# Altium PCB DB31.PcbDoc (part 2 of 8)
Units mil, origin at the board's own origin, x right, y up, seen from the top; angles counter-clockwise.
Board outline 3236.22 x 4456.69 mil, 8 copper layers (Top Layer, MidLayer1, MidLayer2, GND-Layer5, MidLayer3, VCC, MidLayer4, Bottom Layer), stack 61.8 mil thick; 226 components, 469 nets, 1815 pads, 1562 vias.
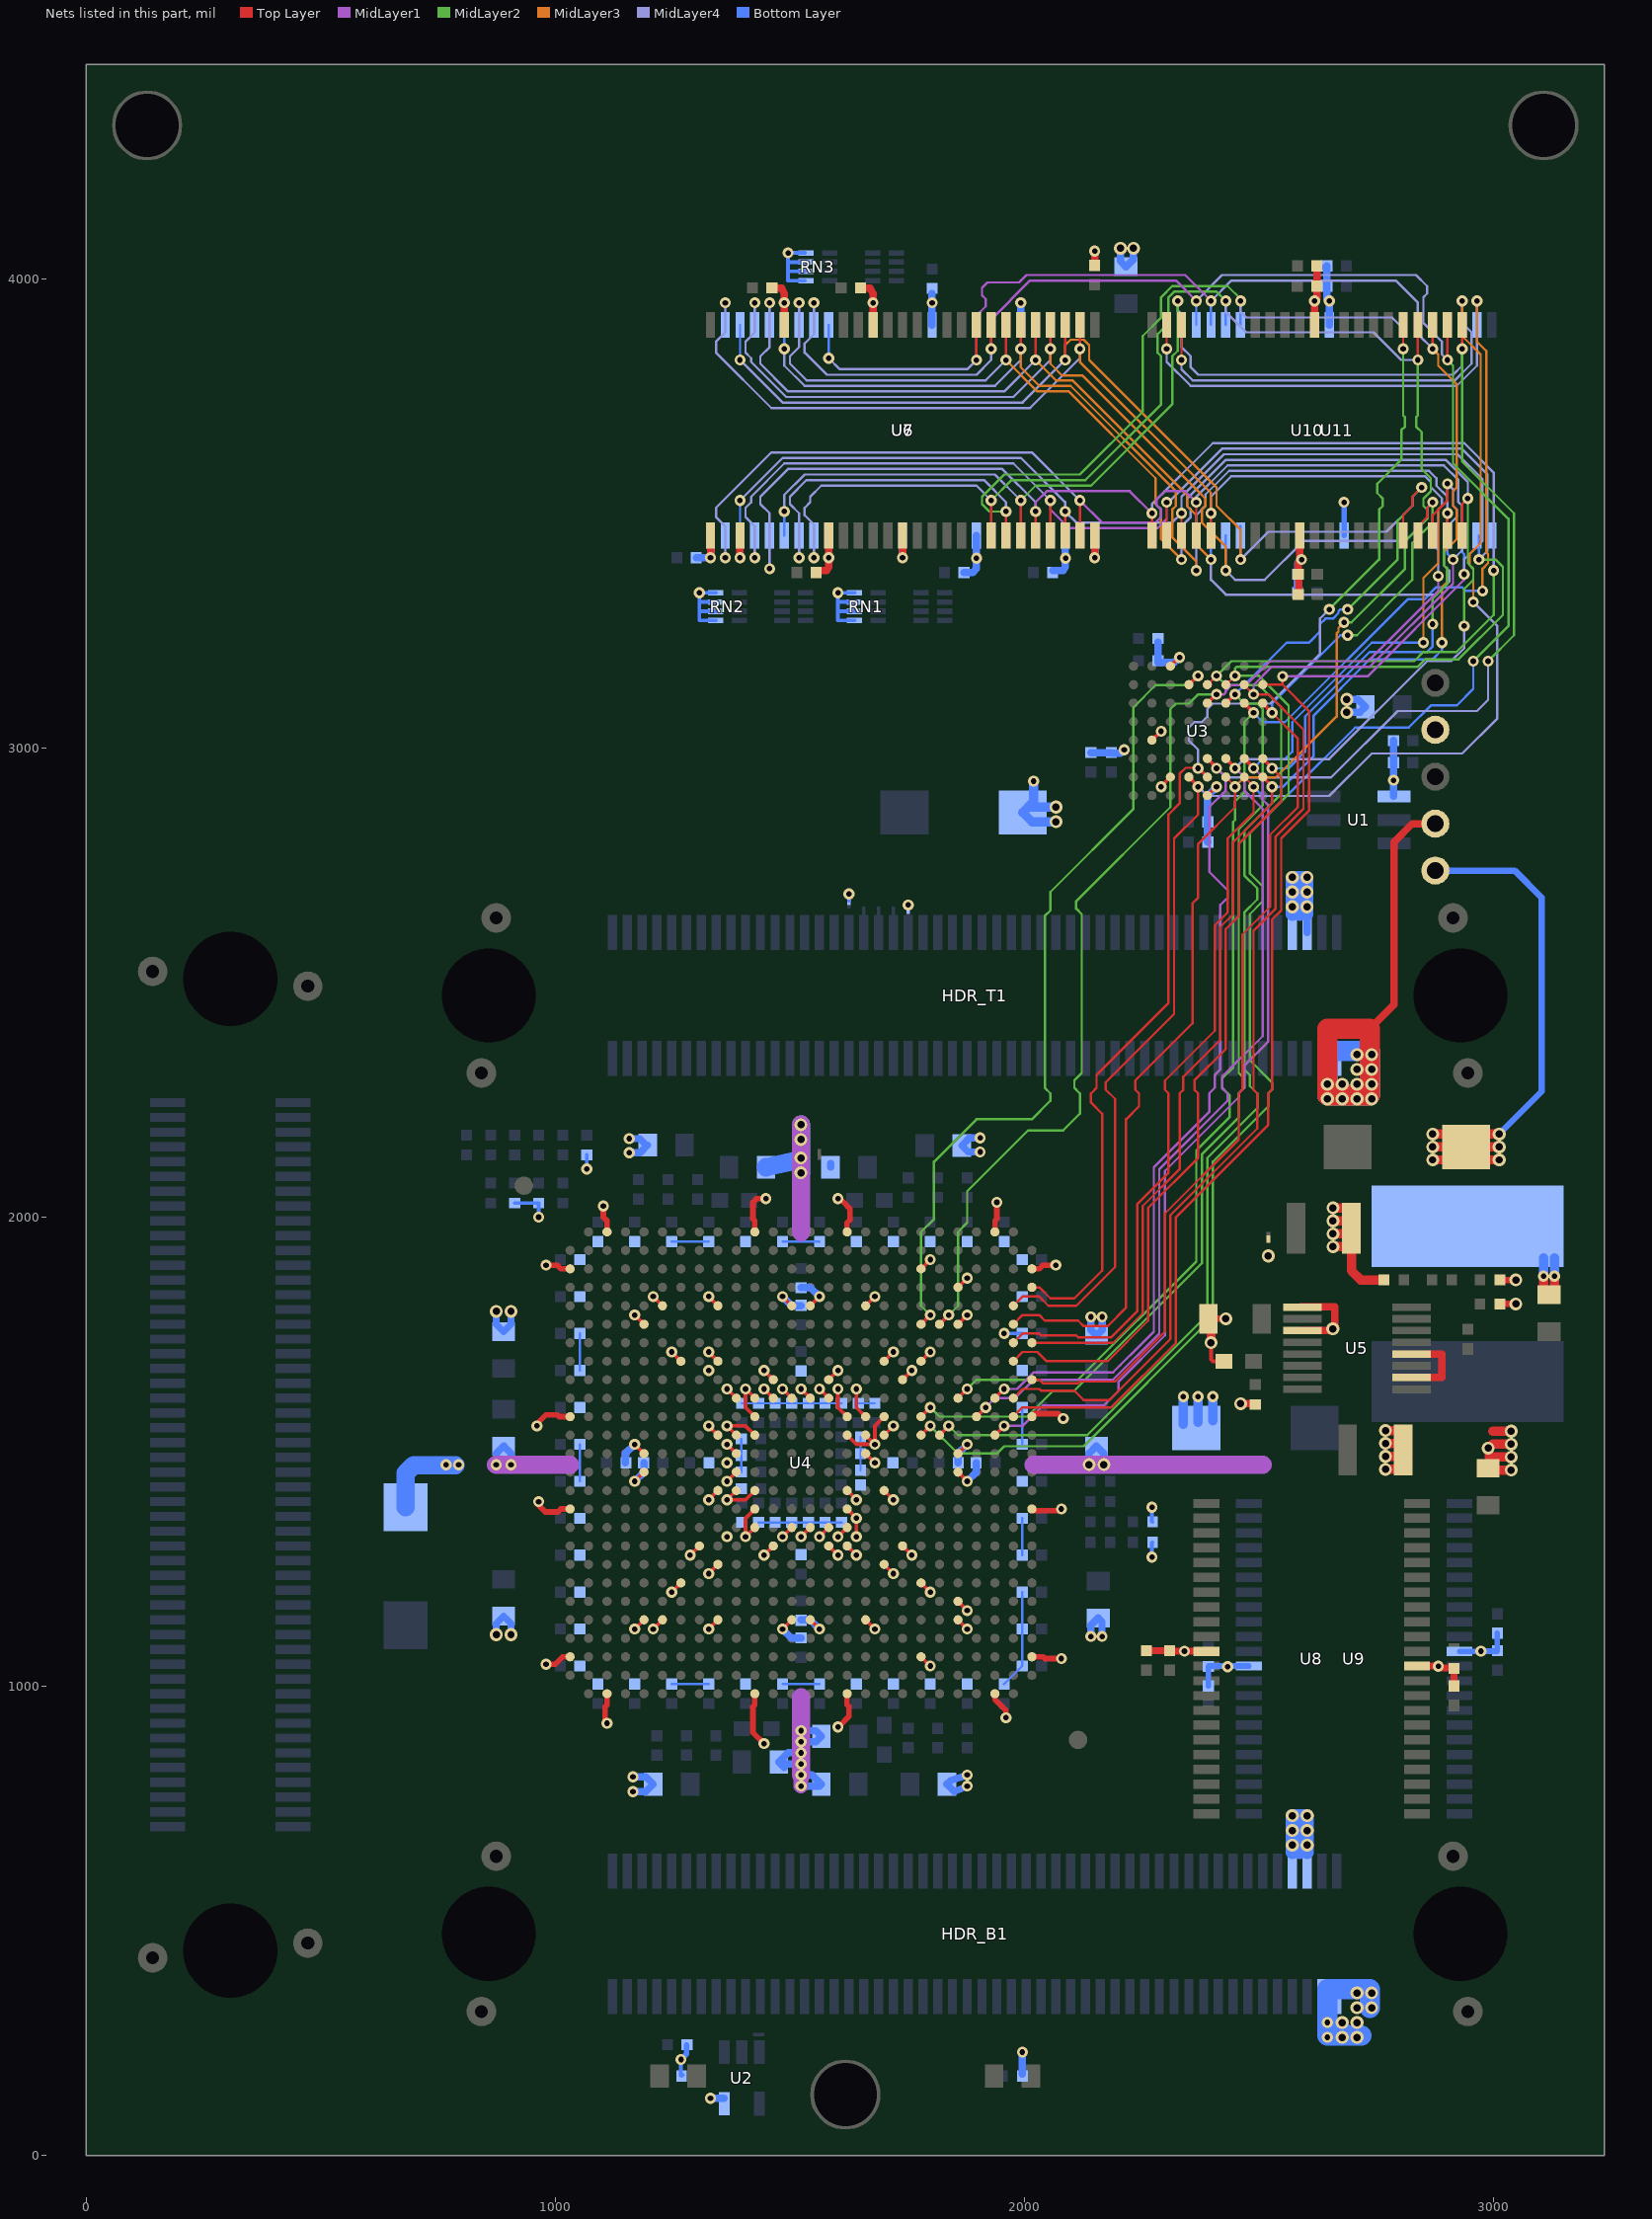
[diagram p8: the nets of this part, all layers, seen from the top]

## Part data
"Altium Logo Bot1" "Altium Logo Top1": library part D-000-0003, "Altium Logo for PCB"
C1 C7 C8 C9 C10 C11 C12 C13 C14 C15 C16 C17 C18 C19 C43 C44 C45 C46 C47 C48 C49 C50 C51 C52 C53 C54 C55 C56 C57 C58 C101 C102 C103 C107 C108 C112 C116 C120 C134 C135 C136 C137 C142 C143 C146 C147 C150 C151 C152 C153: library part D-101-0080, "Capacitor, Ceramic, 0.1uF 10% 16V 0402 (1005) X7R"
C2 C20 C21 C22 C23 C24 C25 C26 C27 C28 C29 C30 C31 C32 C33 C34 C59 C60 C61 C62 C63 C64 C65 C66 C67 C68 C69 C70 C71 C72 C73 C74 C75 C76 C77 C78 C79 C80 C81 C82 C83 C84 C85 C86 C87 C88 C89 C90 C91 C92 C93 C94 C95 C96 C97 C98 C104 C105 C106 C109 C113 C117 C121 C138 C139 C140 C141 C144 C145 C148 C149 C154 C155 C156 C157: library part D-101-0077, "Capacitor, Ceramic, 10nF 10% 16V 0402 (1005) X7R"
C3 C99 C100 C128: library part D-101-0088, "Capacitor, Tantalum, 220uF 10% 10V MCCT-D (7343-31)"
C4 C5 C6 C35 C36 C37 C38 C39 C40 C41 C42 C124 C125 C129 C131: library part D-101-0087, "Capacitor, Ceramic, 10uF 10% 10V 0805 (2012) X5R"
C110 C114 C118 C122: library part D-101-0030, "Capacitor, Ceramic, 1nF 10% 50V 0402 (1005) X7R"
C111 C115 C119 C123 C127: library part D-101-0095, "Capacitor, Ceramic, 2.2uF 10% 10V 0603 (1608) X5R"
C126: library part D-101-0069, "Capacitor, Ceramic, 470pF 5% 50V 0402 (1005) COG"
C130 C132: library part D-101-0021, "Capacitor, Ceramic, 22uF -20%/+80% 10V 1210 (3225) Y5V"
C133: library part D-101-0027, "Capacitor, Ceramic, 1uF 10% 25V 1206 (3216) X7R"
HDR_B1 HDR_L1 HDR_T1: library part D-300-0025, "Connector, Molex Docking Station 100 Pin Male 54075"
L1 L2 L3 L4: library part D-102-0002, "Inductor, Ferrite Bead 1K@100MHz 300mA 0805 (2012) BMB2A1000LN2"
L5: library part D-102-0004, "Inductor, 2.2uH, 15A, 4R2, SMD"
LED1: library part D-153-0004, "LED, Green 0805 (2012) KP-2012SGD"
LED2: library part D-153-0003, "LED, Red 0805 (2013) HSMH-C170"
MH1 MH2 MH3: library part D-001-0001, "Mounting Hole, M3 Screw, Plated, Square Pad"
NT1 NT2 NT3 NT4 NT5 NT6 NT7 NT8: library part D-002-0002, "Net-Tie, Surface Mount, 2 x 0.4mm x 0.2mm SMT Pads - For 0.2mm Track"
R1 R2: library part D-100-0111, "Resistor, 270R 1% 0402 (1005)"
R3 R4 R5 R8 R11: library part D-100-0088, "Resistor, 4K7 1% 0402 (1005)"
R6 R7 R9 R10 R12 R13 R14 R15 R16 R17 R18: library part D-100-0131, "Resistor, 100R 1% 0402 (1005)"
R19: library part D-100-0128, "Resistor, 10R 1% 0402 (1005)"
R20 R22: library part D-100-0105, "Resistor, 2K7 1% 0402 (1005)"
R21: library part D-100-0109, "Resistor, 27K 1% 0402 (1005)"
R23: library part D-100-0132, "Resistor, 100K 1% 0402 (1005)"
RN1 RN2 RN3 RN4 RN5 RN6: library part D-104-0001, "Resistor Network, Isolated, 4 x 100R, 5%, SMD 0402 x 4"
TP1 TP2 TP3 TP4 TP5: library part D-006-0000, "Test Point, PCB Mount with Silkscreen Box"
U1: library part D-263-0002, "Dual Addressable Switch Plus 1KB Memory"
U2: library part D-205-0001, "SN74LVC1G04DBV, Single Inverter Gate, 1.65-V to 5.5-V"
U3: library part D-262-0001, "S29GL256N11FFIV10, 256 Megabit (16M x 16) 3.0V Page Mode Flash Memory"
U4: library part D-241-0004, "FPGA, Altera Cyclone2-35 F672"
U5: library part D-204-0002, "MAX1831EEE, 3A, 1MHz, Low-Voltage, Step-Down Regulators with Synchronous Rectification and Internal Switches"
U6 U7: library part D-261-0000, "MT48LC16M16A2TG, 256 Mbit High-Speed CMOS SDRAM, 16Mb x 16Bit x 4 Banks, TSOP54"
U8 U9 U10 U11: library part D-260-0000, "K6R4016V1D-TC10T, 256K x 16-Bit SRAM, TSOP44"

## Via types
v1: diameter 23.62, hole 11.81, Top Layer to Bottom Layer, 947 vias
v2: diameter 23.62, hole 11.81, Top Layer to Bottom Layer, tented both sides, 476 vias
v3: diameter 27.56, hole 15.75, Top Layer to Bottom Layer, 138 vias
v4: diameter 23.62, hole 11.81, Top Layer to Bottom Layer, tented top, 1 vias

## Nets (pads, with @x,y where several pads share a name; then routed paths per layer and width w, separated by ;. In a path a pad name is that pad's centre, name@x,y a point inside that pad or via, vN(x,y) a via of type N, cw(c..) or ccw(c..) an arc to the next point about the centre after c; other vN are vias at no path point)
1V2: C3.1 C4.1 C5.1 C6.1 C7.1 C8.1 C9.1 C10.1 C11.1 C12.1 C13.1 C14.1 C15.1 C16.1 C17.1 C18.1 C19.1 C20.1 C21.1 C22.1 C23.1 C24.1 C25.1 C26.1 C27.1 C28.1 C29.1 C30.1 C31.1 C32.1 C33.1 C34.1 C128.1 C131.1 C132.1 L1.1 L2.1 L3.1 L4.1 L5.2 R20.1 TP5.1 U4.H7 U4.H20 U4.K10 U4.K11 U4.K12 U4.K13 U4.K14 U4.K15 U4.L11 U4.L16 U4.L17 U4.L18 U4.M10 U4.M11 U4.M16 U4.M17 U4.N10 U4.N17 U4.P10 U4.R10 U4.R11 U4.R16 U4.T11 U4.T16 U4.U11 U4.U13 U4.U14 U4.U15 U4.U16 U4.V16 U4.Y7 U4.Y20 | length 5461.1
  Top Layer w7.87: v1(1248.03,1200.78) U4.Y7@1267.72,1220.47 ; v1(1248.03,1712.6) U4.H7@1267.72,1692.91 ; v1(1366.14,1437.01) U4.P10@1385.83,1456.69 ; v1(1366.14,1515.75) U4.N10@1385.83,1496.06 ; v1(1366.14,1633.86) U4.K10@1385.83,1614.17 ; U4.R10@1385.83,1417.32 v1(1366.14,1397.64) 1405.51,1397.64 U4.R11@1425.2,1417.32 ; U4.M10@1385.83,1535.43 v1(1366.14,1555.12) 1405.51,1555.12 U4.M11@1425.2,1535.43 ; U4.U11@1425.2,1338.58 v1(1405.51,1318.9) 1405.51,1358.27 U4.T11@1425.2,1377.95 ; U4.L11@1425.2,1574.8 1405.51,1594.49 v1(1405.51,1633.86) U4.K11@1425.2,1614.17 ; v1(1444.88,1633.86) U4.K12@1464.57,1614.17 ; v1(1484.25,1318.9) U4.U13@1503.94,1338.58 ; v1(1484.25,1633.86) U4.K13@1503.94,1614.17 ; v1(1523.62,1318.9) U4.U14@1543.31,1338.58 ; v1(1523.62,1633.86) U4.K14@1543.31,1614.17 ; v1(1562.99,1318.9) U4.U15@1582.68,1338.58 ; v1(1562.99,1633.86) U4.K15@1582.68,1614.17 ; v1(1602.36,1318.9) U4.U16@1622.05,1338.58 ; v1(1602.36,1633.86) 1602.36,1594.49 U4.L16@1622.05,1574.8 ; U4.V16@1622.05,1299.21 v1(1641.73,1279.53) ; U4.T16@1622.05,1377.95 v1(1641.73,1358.27) v1(1641.73,1318.9) ; U4.R16@1622.05,1417.32 v1(1641.73,1397.64) ; U4.M16@1622.05,1535.43 1641.73,1515.75 v1(1681.1,1515.75) ; v1(1641.73,1633.86) 1641.73,1594.49 U4.L17@1661.42,1574.8 ; U4.N17@1661.42,1496.06 v1(1681.1,1476.38) ; U4.M17@1661.42,1535.43 v1(1681.1,1515.75) ; U4.L18@1700.79,1574.8 1681.1,1555.12 v1(1681.1,1515.75) ; U4.Y20@1779.53,1220.47 v1(1799.21,1200.78) ; U4.H20@1779.53,1692.91 v1(1799.22,1712.6)
  Top Layer w19.68: C132.1@2692.91,1976.37 C132.1@2694.88,1974.41 ; C132.1@2696.85,1948.82 2696.85,1976.37 2696.85,1885.83 2716.54,1866.14 R20.1@2766.21,1866.14 ; v3@2866.14,2122.05 C128.1@2913.39,2122.05 ; v3(2870.08,2149.61) C128.1@2937.01,2149.61 ; v3(2870.08,2177.17) C128.1@2937.01,2177.17 ; C128.1@2941.3,2122.05 v3(3011.81,2122.05) ; C128.1@2941.3,2149.61 v3(3011.81,2149.61) ; C128.1@2968.3,2122.05 C128.1@2941.02,2149.33 2968.86,2177.17 v3(3011.81,2177.17) ; C131.1@3106.3,1834.65 v1(3106.3,1874.02) ; C131.1@3129.92,1834.65 v1(3129.92,1874.02)
  Top Layer w20: v3(2657.47,1937) C132.1@2696.85,1937 ; v3(2657.47,1964.56) C132.1@2696.85,1964.56 ; v3(2657.47,1992.12) C132.1@2696.85,1992.12 ; v3(2657.47,2019.68) C132.1@2696.85,2019.68
  MidLayer1 w31.5: v1(1523.62,787.4) v1(1523.62,811.02)
  MidLayer1 w39.37: v1(874.02,1472.44) 1031.5,1472.44 ; v1(1523.62,811.02) 1523.62,976.38 ; 1523.62,1968.5 v3(1523.62,2196.85) ; 2019.68,1472.44 2507.87,1472.44
  Bottom Layer w5: C30.1@1396.65,1456.69 C18.1@1396.65,1492.12 C19.1@1396.65,1527.56 ; C7.1@1397.64,1603.34 C20.1@1433.07,1603.34 C8.1@1468.5,1603.34 C21.1@1503.93,1603.34 C9.1@1539.37,1603.34 C22.1@1574.8,1603.34 C10.1@1610.23,1603.34 ; C16.1@1433.07,1349.41 C28.1@1468.5,1349.41 C15.1@1503.93,1349.41 C27.1@1539.37,1349.41 C14.1@1574.8,1349.41 C26.1@1610.23,1349.41 ; C23.1@1645.67,1603.34 C11.1@1681.1,1603.34 ; C25.1@1650.59,1460.63 C12.1@1650.59,1496.06 C24.1@1650.59,1531.49
  Bottom Layer w13.78: TP5.1@2875.71,2738.67 3044.8,2738.67 3102.36,2681.1 3102.36,2625.98 3102.36,2267.72 v3(3011.81,2177.17)
  Bottom Layer w15.75: v1(874.02,1472.44) 874.02,1496.06 C4.1@889.76,1511.81 905.51,1496.06 v1(905.51,1472.44) ; L1.1@1488.18,826.77 L1.1@1476.38,838.58 1496.06,858.27 v1(1523.62,858.27) ; L1.1@1488.18,834.65 v1(1523.62,834.65) ; v3@1519.68,2122.05 v3(1523.62,2125.98) ; v1(1523.62,787.4) 1562.99,787.4 C5.1@1566.93,791.34 1547.24,811.02 v1(1523.62,811.02) ; v1(1523.62,881.89) 1555.12,881.89 L4.1@1566.93,893.7 1555.11,905.51 v1(1523.62,905.51) ; L2.1@1586.61,2106.29 L2.1@1586.61,2114.18 ; v3(2137.8,1472.44) 2137.8,1496.06 C6.1@2153.54,1511.81 2169.29,1496.06 v3(2169.29,1472.44)
  Bottom Layer w19.68: v1(3106.3,1874.02) L5.2@3106.3,1913.39 ; v1(3129.92,1874.02) L5.2@3129.92,1913.39
  Bottom Layer w20: C3.1@2338.59,1558.51 v1(2338.59,1617.56) ; C3.1@2370.08,1562.45 v1(2370.08,1617.56) ; C3.1@2401.58,1566.38 v1(2401.58,1617.56)
  Bottom Layer w39.37: L3.1@1448.82,2106.29 1517.6,2121.58 v3@1519.68,2122.05 ; v3(1523.62,2094.49) v3(1523.62,2196.85)
  other v1: 1366.14,1318.9 1366.14,1476.38 1326.77,1673.23
  other v3: 2870.08,2122.05 1523.62,2165.35
3V3: C1.2 C2.1 C35.1 C36.1 C37.1 C38.1 C39.1 C40.1 C41.1 C42.1 C43.1 C44.1 C45.1 C46.1 C47.1 C48.1 C49.1 C50.1 C51.1 C52.1 C53.1 C54.1 C55.1 C56.1 C57.1 C58.1 C59.1 C60.1 C61.1 C62.1 C63.1 C64.1 C65.1 C66.1 C67.1 C68.1 C69.1 C70.1 C71.1 C72.1 C73.1 C74.1 C75.1 C76.1 C77.1 C78.1 C79.1 C80.1 C81.1 C82.1 C83.1 C84.1 C85.1 C86.1 C87.1 C88.1 C89.1 C90.1 C91.1 C92.1 C93.1 C94.1 C95.1 C96.1 C97.1 C98.1 C99.1 C100.1 C101.2 C102.1 C103.1 C104.1 C105.1 C106.1 C107.1 C124.1 C125.1 C134.1 C135.1 C136.1 C137.1 C138.1 C139.1 C140.1 C141.1 C142.1 C143.1 C144.1 C145.1 C146.1 C147.1 C148.1 C149.1 C150.1 C151.1 C152.1 C153.1 C154.1 C155.1 C156.1 C157.1 HDR_B1.94 HDR_B1.96 HDR_T1.94 HDR_T1.96 NT1.2 NT4.2 R1.1 R2.1 R3.2 R4.2 R5.2 R8.2 R11.2 RN1.1 RN1.2 RN1.3 RN1.4 RN2.1 RN2.2 RN2.3 RN2.4 RN3.1 RN3.2 RN3.3 RN3.4 TP2.1 U1.4 U2.5 U3.D8 U3.F1 U3.F7 U3.G5 U4.A3 U4.A11 U4.A16 U4.A24 U4.AA22 U4.AB5 U4.AB6 U4.AB9 U4.AB13 U4.AB14 U4.AB17 U4.AB22 U4.AD1 U4.AD20 U4.AD26 U4.AF3 U4.AF11 U4.AF16 U4.AF24 U4.C1 U4.C20 U4.C26 U4.D22 U4.E6 U4.E9 U4.E13 U4.E14 U4.E17 U4.F5 U4.F22 U4.H9 U4.H18 U4.J12 U4.J15 U4.J19 U4.L1 U4.L26 U4.M9 U4.M18 U4.N5 U4.N22 U4.P5 U4.P22 U4.R9 U4.R18 U4.T1 U4.T26 U4.V8 U4.V12 U4.V15 U4.V19 U4.W9 U4.W18 U6.1 U6.3 U6.9 U6.14 U6.27 U6.43 U6.49 U7.1 U7.3 U7.9 U7.14 U7.27 U7.43 U7.49 U8.11 U8.33 U9.11 U9.33 U10.11 U10.33 U11.11 U11.33 | length 8907.4
  Top Layer w5: U6.9@1582.68,3433.07 U6.9@1582.68,3452.76
  Top Layer w7.87: v1(1169.29,1122.04) U4.AB5@1188.98,1141.73 ; v1(1169.29,1437.01) U4.P5@1188.98,1456.69 ; v1(1169.29,1515.75) U4.N5@1188.98,1496.06 ; v1(1169.29,1791.34) U4.F5@1188.98,1771.65 ; v1(1208.66,1122.04) U4.AB6@1228.35,1141.73 ; v1(1208.66,1830.71) U4.E6@1228.35,1811.02 ; v1(1287.4,1279.53) U4.V8@1307.09,1299.21 ; v1(1326.77,1122.04) U4.AB9@1346.46,1141.73 ; v1(1326.77,1240.16) U4.W9@1346.46,1259.84 ; v1(1326.77,1397.64) U4.R9@1346.46,1417.32 ; v1(1326.77,1555.12) U4.M9@1346.46,1535.43 ; v1(1326.77,1712.6) U4.H9@1346.46,1692.91 ; v1(1326.77,1830.71) U4.E9@1346.46,1811.02 ; v1(1444.88,1279.52) U4.V12@1464.57,1299.21 ; v1(1444.88,1673.23) U4.J12@1464.57,1653.54 ; v1(1484.25,1122.04) U4.AB13@1503.94,1141.73 ; v1(1484.25,1830.71) U4.E13@1503.94,1811.02 ; U4.AB14@1543.31,1141.73 v1(1562.99,1122.04) ; U4.E14@1543.31,1811.02 v1(1562.99,1830.71) ; U4.V15@1582.68,1299.21 v1(1602.36,1279.53) ; U4.J15@1582.68,1653.54 v1(1602.36,1673.23) ; U4.AB17@1661.42,1141.73 v1(1681.1,1122.04) ; U4.E17@1661.42,1811.02 v1(1681.1,1830.71) ; U4.W18@1700.79,1259.84 v1(1720.47,1240.16) ; U4.R18@1700.79,1417.32 v1(1720.47,1397.64) ; U4.M18@1700.79,1535.43 v1(1720.47,1555.12) ; U4.H18@1700.79,1692.91 v1(1720.47,1712.6) ; U4.V19@1740.16,1299.21 v1(1759.84,1279.53) ; U4.J19@1740.16,1653.54 v1(1759.84,1673.23) ; U4.AD20@1779.53,1062.99 v1(1799.21,1043.3) ; U4.C20@1779.53,1889.76 v1(1799.21,1909.45) ; U4.AB22@1858.27,1141.73 v1(1877.95,1122.04) ; U4.AA22@1858.27,1181.1 v1(1877.96,1161.41) ; U4.P22@1858.27,1456.69 v1(1877.96,1437.01) ; U4.N22@1858.27,1496.06 v1(1877.96,1515.75) ; U4.F22@1858.27,1771.65 v1(1877.96,1791.34) ; U4.D22@1858.27,1850.39 v1(1877.96,1870.08) ; U3.G5@2271.65,3016.73 v1(2291.34,3035.43) ; v1@2291.34,2918.31 U3.F7@2311.02,2937.99 ; U3.F1@2311.02,3174.21 v1@2330.71,3193.9 ; U3.D8@2389.76,2898.62 v1@2409.45,2918.31
  Top Layer w11.81: v1(960.63,1555.12) 960.63,1559.06 980.31,1578.74 1003.94,1578.74 1007.87,1574.8 U4.L1@1031.5,1574.8 ; v1(964.57,1393.7) 964.57,1385.83 978.72,1371.67 1005.53,1371.67 1011.81,1377.95 U4.T1@1031.5,1377.95 ; v1(980.31,1047.24) 1000,1047.24 1015.75,1062.99 U4.AD1@1031.5,1062.99 ; v1(980.31,1897.64) 1003.94,1897.64 1011.81,1889.76 U4.C1@1031.5,1889.76 ; v1(1102.36,2023.62) 1102.36,2000 1110.24,1992.13 U4.A3@1110.24,1968.5 ; v1(1110.24,921.26) 1106.3,925.2 1106.3,956.69 1110.24,960.63 U4.AF3@1110.24,984.25 ; U4.AF11@1425.2,984.25 1425.2,960.63 1421.26,956.69 1421.26,901.57 v1(1444.88,877.95) ; U4.A11@1425.2,1968.5 1425.2,1992.13 1421.26,1996.06 1421.26,2031.5 1429.13,2039.37 v1(1448.82,2039.37) ; v1(1602.36,2039.37) 1610.24,2035.43 1628.33,2017.34 1628.33,1994.47 1622.05,1988.19 U4.A16@1622.05,1968.5 ; v1@1602.85,912.89 1625.98,936.02 1625.98,956.69 1622.05,960.63 U4.AF16@1622.05,984.25 ; U4.AF24@1937.01,984.25 1937.01,972.44 1960.63,948.82 v1(1960.63,933.07) ; U4.A24@1937.01,1968.5 1937.01,1992.13 1940.94,1996.06 v1@1940.94,2026.56 ; U4.AD26@2015.75,1062.99 2039.37,1062.99 2043.31,1059.06 v1(2078.74,1059.06) ; U4.T26@2015.75,1377.95 2019.69,1374.02 2074.8,1374.02 v1(2078.74,1377.95) ; U4.L26@2015.75,1574.8 2022.03,1581.08 2072.46,1581.08 v1(2082.68,1570.87) ; U4.C26@2015.75,1889.76 2031.5,1889.76 2039.37,1897.64 v1(2066.93,1897.64)
  Top Layer w15: C145.1@2259.84,1075.78 C143.1@2309.14,1075.78 2309.92,1075 2343,1075 2343.2,1074.8 U8.33@2387.89,1074.8 ; U8.11@2836.71,1043.3 2885.83,1043.3 2889.76,1039.37 2914.45,1039.37 C142.1@2915.44,1038.38 C144.1@2915.44,1000.97 ; v1@2881.7,1043.3 v1(2882,1043)
  Top Layer w15.75: v2@1330.71,3409.45 U6.1@1330.71,3452.76 ; v2(1393.7,3405.51) U6.3@1393.7,3452.76 ; C138.1@1461.61,3980.31 1482.28,3980.32 1488.19,3968.51 ; U6.49@1488.19,3901.57 v2(1488.19,3948.82) ; v2@1488.19,3944.88 1488.19,3964.57 ; C135.1@1556.1,3377.95 1578.74,3377.95 1582.68,3385.83 1582.68,3389.76 1583.46,3401.52 1583.58,3403.35 v2@1583.66,3404.53 ; U6.9@1582.68,3452.76 v2@1582.68,3409.45 ; C139.1@1650.59,3980.31 1671.26,3980.32 1677.17,3968.51 v2@1677.17,3944.88 ; U6.43@1677.17,3901.57 v2(1677.17,3948.82) ; v2(1740.16,3405.51) U6.14@1740.16,3452.76 ; v2(2149.6,3405.52) U6.27@2149.61,3452.76 ; C134.1@2149.6,4028.54 v2(2149.61,4059.06) ; C154.1@2582.4,3371.05 C154.1@2583.38,3370.07 2583.38,3394.4 v2(2590.55,3401.57) 2586.61,3405.51 U10.11@2586.61,3452.76 ; C150.1@2584.37,3329.71 2584.37,3370.07 C154.1@2584.34,3370.23 ; U10.33@2618.11,3901.57 v2(2618.11,3952.76) 2623.03,3957.67 C151.1@2623.03,4027.55 ; v2@1582.68,3409.45 v2@1583.43,3405.66 ; v2@1582.68,3409.45 v2@1583.43,3405.66 ; v2@1583.43,3405.66 v2@1583.66,3404.53 ; v2@1583.43,3405.66 v2@1583.66,3404.53
  MidLayer4 w5: v3(2570.87,661.42) v3@2570.87,665.36
  Bottom Layer w5: C93.1@1052.17,1437.01 C94.1@1052.17,1515.75 ; C71.1@1052.17,1673.23 C67.1@1052.17,1751.97 ; C81.1@1248.03,1004.92 C80.1@1326.77,1004.92 ; C66.1@1248.03,1947.83 C64.1@1326.77,1947.83 ; C87.1@1484.25,1004.92 C84.1@1562.99,1004.92 ; C91.1@1484.25,1947.83 C98.1@1562.99,1947.83 ; C90.1@1956.7,1004.92 C88.1@1995.08,1043.31 C52.1@1995.08,1122.05 C54.1@1995.08,1200.79 ; C51.1@1995.08,1279.53 C97.1@1995.08,1358.27 ; C53.1@1995.07,1515.74 C58.1@1995.07,1594.49
  Bottom Layer w7.87: R11.2@913.38,2030 R4.2@964.56,2030 v1(964.57,2000) ; v1(1066.93,2102.36) R3.2@1066.93,2132.36 ; v1(1267.72,204.72) 1267.72,170.78 R1.1@1269.21,169.29 R1.1@1271.65,171.73 ; C101.2@1279.53,235.24 C101.2@1280.51,236.22 ; 1307.09,3291.34 RN2.2@1342.51,3291.34 ; 1307.09,3311.02 RN2.3@1342.51,3311.02 ; RN2.1@1342.51,3271.65 1307.09,3271.65 v1(1307.09,3330.71) RN2.4@1342.51,3330.71 ; U2.5@1359.25,122.05 U2.5@1360.23,123.03 ; 1496.07,4015.74 RN3.2@1531.49,4015.74 ; 1496.07,4035.43 RN3.3@1531.49,4035.43 ; RN3.1@1531.49,3996.06 1496.07,3996.06 v1(1496.07,4055.11) RN3.4@1531.49,4055.11 ; 1602.36,3291.34 RN1.2@1637.79,3291.34 ; 1602.36,3311.02 RN1.3@1637.79,3311.02 ; NT1.2@1625.98,2674.29 v2(1625.98,2688.98) ; RN1.1@1637.79,3271.65 1602.36,3271.65 v1(1602.36,3330.71) RN1.4@1637.79,3330.71 ; NT4.2@1751.97,2657.48 v2(1751.97,2665.35) ; v1@1877.95,807.08 v1(1877.95,811.02) ; v1(1956.7,1751.97) C56.1@1995.08,1751.97 ; v1(2271.65,1275.59) 2271.65,1305.59 R8.2@2273.15,1307.08 ; v1(2271.65,1381.89) 2271.65,1351.88 R5.2@2273.15,1350.39
  Bottom Layer w11.81: v1(1267.72,204.72) 1279.53,216.54 C101.2@1279.53,235.24 ; C146.1@2391.82,1000.97 C148.1@2391.82,1042.31 2392.81,1043.3 U9.11@2478.44,1043.3 ; v1(2433,1042) v1@2434.3,1043.3 ; U11.11@2681.1,3452.76 v2(2681.1,3523.62) ; U9.33@2927.25,1074.79 2972.79,1074.79 v1(2973,1075) 3007.08,1075 C149.1@3007.87,1075.79 C147.1@3007.87,1113.19
  Bottom Layer w15: v3(874.02,1110.24) 874.02,1133.86 C38.1@889.76,1149.6 905.51,1133.85 v3(905.51,1110.24) ; v3(874.02,1799.21) 874.02,1771.65 C36.1@889.76,1755.9 905.51,1771.65 v3(905.51,1799.21) ; v1(1157.6,2137.24) 1180.55,2137.24 C35.1@1196.85,2153.54 ; v1(1157.6,2167.24) 1180.06,2167.24 C35.1@1193.06,2154.24 ; v2(1165.35,775.59) 1192.91,775.59 C42.1@1208.66,791.34 1192.91,807.09 v2(1165.35,807.09) ; C41.1@1834.64,791.34 1850.39,775.59 v1(1877.95,787.4) ; v1(1905.51,2138.86) 1879.96,2138.84 C37.1@1866.26,2152.54 1882.57,2168.84 v1(1905.51,2168.86) ; C40.1@2157.48,1145.67 2165.35,1137.79 v1(2165.35,1106.3)
  Bottom Layer w15.75: C44.1@1149.6,1476.38 1149.6,1496.06 v1(1169.29,1515.75) ; v1(1169.29,1437.01) 1188.98,1456.69 C45.1@1188.98,1476.38 ; C136.1@1300.19,3405.5 v2(1330.71,3405.51) ; U7.27@1329.73,3437.99 U7.27@1330.71,3437.01 ; v1(1330.71,122.05) U2.5@1359.25,122.05 ; v2@1330.71,3404.53 U7.27@1330.71,3452.76 ; v1(1484.25,1122.04) 1503.94,1102.36 C43.1@1523.63,1102.36 ; v1(1484.25,1830.71) 1503.94,1811.02 C47.1@1523.63,1811.02 ; C48.1@1523.62,1141.73 1543.31,1141.73 v1(1562.99,1122.04) ; C49.1@1523.62,1850.4 1543.31,1850.4 v1(1562.99,1830.71) ; v2(1740.16,3405.51) U7.14@1740.16,3452.76 ; U7.43@1803.15,3901.57 C137.1@1803.15,3968.5 ; C41.1@1834.64,791.34 1842.52,799.21 v1(1877.95,811.02) ; C50.1@1858.27,1476.38 1858.27,1496.06 v1(1877.96,1515.75) ; C141.1@1871.06,3374.01 1889.76,3374.01 1897.64,3381.89 v2(1897.64,3404.53) 1897.64,3405.51 U7.9@1897.64,3452.76 ; v1(1877.96,1437.01) 1897.64,1456.69 C46.1@1897.64,1476.38 ; U7.49@1992.13,3901.57 v2(1992.13,3948.82) ; R2.1@1995.59,173.23 v1(1995.59,220.47) ; C140.1@2060.05,3377.95 2082.68,3377.95 2086.62,3385.83 2086.62,3389.76 U7.3@2086.61,3452.76 ; v2@2086.62,3409.45 v2(2087.6,3404.53) ; v1(2141.73,1106.3) 2141.73,1129.92 C40.1@2157.48,1145.67 ; v4(2141.73,1787.4) 2141.73,1759.83 C39.1@2153.54,1748.03 2165.35,1759.84 v1(2165.35,1787.4) ; C107.1@2141.73,2990.16 C104.1@2185.04,2990.16 2186.02,2989.18 2204.73,2989.18 v1(2212.6,2996.06) ; v2(2149.6,3405.52) 2149.61,3409.45 U7.1@2149.61,3452.76 ; v3(2204.72,4064.96) 2204.72,4037.4 C125.1@2216.53,4025.58 2232.28,4041.34 v3(2232.28,4064.96) ; C103.1@2284.45,3225.39 2284.45,3182.09 2318.9,3182.09 v1@2330.71,3193.9 ; C102.1@2390.74,2799.21 2389.76,2800.19 2389.76,2897.64 v1@2409.45,2917.33 ; C152.1@2581.69,3330.7 C156.1@2581.69,3370.07 2582.68,3371.06 2582.68,3393.7 v2(2590.55,3401.57) ; HDR_T1.96@2602.36,2606.3 2602.36,2645.67 ; C153.1@2641.73,4024.61 C153.1@2644.68,4027.55 2644.68,3957.68 v2(2649.61,3952.76) v2@2649.61,3956.7 ; U11.33@2649.88,3901.57 v2@2649.88,3944.88 ; v3(2687.01,3075.79) 2714.58,3075.79 C124.1@2726.38,3087.59 2710.63,3103.35 v3(2687.01,3103.35) ; U1.4@2786.42,2897.63 C1.2@2786.41,3015.74
  Bottom Layer w19.68: C100.1@2007.68,2874.02 v3(2066.93,2874.02) ; v1(2019.68,2929.13) 2019.68,2886.02 C100.1@1996.14,2862.47 2016.09,2842.52 v3(2066.93,2842.52)
  Bottom Layer w27.56: 2570.87,645.67 v3(2570.87,661.42) v3(2570.87,692.91) v3(2570.87,724.41) v3(2602.37,724.41) v3(2602.37,692.91) v3(2602.37,661.42) 2602.36,645.67 ; 2570.87,2645.67 v3(2570.87,2724.41) v3(2602.36,2724.41) 2602.36,2645.67 ; 2586.62,645.67 2586.62,724.41 ; 2586.61,2645.67 2586.61,2724.41
  Bottom Layer w39.37: C99.1@681.1,1381.89 681.1,1454.1 698,1471 v1@787.32,1471
  other v1: 1602.36,913.39 2341,1075 767.24,1472.44 794.02,1472.44 1940.94,2031.5 2291.34,2917.32 2409.45,2917.32 2330.71,3192.91
  other v2: 2786.42,2931.1 1582.68,3405.51 1803.15,3948.82
  other v3: 2570.87,2661.42 2602.36,2661.42 2570.87,2692.91 2602.36,2692.91
5V0: C129.1 C130.1 HDR_B1.97 HDR_B1.99 HDR_T1.97 HDR_T1.99 R19.1 TP4.1 U5.2 U5.4 | length 2295.6
  Top Layer w15.75: v3(2460.63,1602.36) 2490.62,1602.36 R19.1@2492.12,1600.86 ; 2728.35,2393.7 2787.4,2452.75 2787.4,2799.21 2826.86,2838.67 TP4.1@2875.71,2838.67 ; C130.1@2805.11,1505.9 2803.14,1503.93 C130.1@2818.89,1488.19 ; U5.2@2824.58,1658.25 2889.67,1658.25 2889.67,1708.25 U5.4@2824.58,1708.25 ; C129.1@2988.18,1464.56 v3(2988.19,1507.87)
  Top Layer w20: v3(2769.67,1462.59) C130.1@2809.04,1462.59 ; v3(2769.67,1490.15) C130.1@2809.04,1490.15 ; v3(2769.67,1517.71) C130.1@2809.04,1517.71 ; v3(2769.67,1545.27) C130.1@2809.04,1545.27 ; C129.1@2998.04,1461.1 v3(3037.41,1461.1) ; 2998.04,1488.66 v3(3037.41,1488.66) ; v3@2998.04,1516.22 v3(3037.41,1516.22) ; 2998.04,1543.78 v3(3037.41,1543.78)
  Top Layer w43.31: v3@2645.67,2259.84 2736.22,2259.84 2736.22,2401.57 2645.67,2401.58 v3@2645.67,2259.84
  Bottom Layer w43.31: 2649.61,263.78 v3@2677.17,263.78 ; v3@2716.54,255.91 2718.5,255.91 2708.66,255.91 2677.17,255.9 2645.67,255.9 2645.67,354.33 2736.22,354.33 2736.22,346.46 v3@2736.22,314.96 ; v3@2645.67,2259.84 2736.22,2259.84 2736.22,2283.47 2736.22,2314.96 2736.22,2346.46 2736.22,2354.33 2645.67,2354.33 v3@2645.67,2259.84
  other v1: 2645.67,251.97 2645.67,283.46
  other v3: 2677.17,251.97 2708.66,251.97 2677.17,283.46 2708.66,283.46 2708.66,314.96 2740.16,314.96 2708.66,346.46 2740.16,346.46 2645.67,2251.97 2677.17,2251.97 2708.66,2251.97 2740.16,2251.97 2645.67,2283.46 2677.17,2283.47 2708.66,2283.47 2740.16,2283.47 2708.66,2314.96 2740.16,2314.96 2708.66,2346.46 2740.16,2346.46
AGND: C127.2 C133.1 NT8.1 R22.2 R23.2 U5.9 U5.11 | length 426.1
  Top Layer w7.87: v3(2397.64,1732.28) 2397.64,1696.85 2401.58,1692.91 C127.2@2425.19,1692.91
  Top Layer w13.78: C133.1@2391.73,1783.46 v3(2429.13,1783.46) ; R23.2@3013.3,1814.96 v3(3047.24,1814.96) ; R22.2@3013.3,1866.14 v3(3047.24,1866.14)
  Top Layer w15.75: U5.9@2589.19,1808.68 2591.08,1808.69 2592.58,1808.69 2661.35,1808.87 2661.35,1808.76 ; U5.11@2591.08,1758.25 U5.11@2592.58,1758.25 2653.67,1758.25 v3(2657.19,1761.76) ; 2657.48,1808.76 2661.35,1808.76 ; v3@2661.35,1758.26 2661.35,1761.76 2661.35,1808.76
  Top Layer w19.68: v3(2397.64,1732.28) 2397.64,1777.55 C133.1@2391.73,1783.46 C133.1@2397.64,1789.37
  other v3: 2519.68,1917.32
BUS_A1: U3.E2 U4.F20 | length 1790.5
  Top Layer w7.87: U4.F20@1779.53,1771.65 v1(1799.22,1791.34) ; U3.E2@2350.39,3134.84 v1(2370.08,3153.55)
  MidLayer2 w5: v1(1799.22,1791.34) 1779.53,1811.02 1779.53,1866.14 1779.53,1968.52 1807.09,1996.07 1807.09,2031.49 1807.09,2039.37 1807.09,2118.11 1897.64,2208.66 2015.75,2208.66 2055.12,2248.03 2055.12,2263.78 2043.31,2275.59 2043.31,2641.73 2055.12,2653.54 2055.12,2692.91 2232.28,2870.08 2232.28,3086.61 2279.53,3133.86 2350.39,3133.86 v1(2370.08,3153.55)
BUS_A2: U3.D2 U4.M21 U6.23 U7.23 U10.1 U11.1 | length 5430.9
  Top Layer w5: U6.23@2023.62,3452.76 v2(2023.62,3503.93) ; U10.1@2271.65,3452.76 v1(2271.65,3500) ; U3.D2@2389.76,3134.84 2390.75,3134.85 v1(2409.45,3153.54)
  Top Layer w7.87: U4.M21@1818.9,1535.43 v1(1838.59,1555.12)
  MidLayer1 w5: v2(2023.62,3503.93) 2023.62,3523.62 2047.24,3547.24 2224.41,3547.24 v1(2271.65,3500)
  MidLayer2 w5: v1(1838.59,1555.12) 1858.27,1535.43 1929.14,1535.43 2078.74,1535.43 2090.55,1535.43 2133.86,1535.43 2389.76,1791.34 2389.76,2125.98 2496.06,2232.28 2496.06,2263.78 2480.31,2279.53 2480.31,2303.15 2468.5,2314.96 2468.5,2649.61 2496.06,2677.17 2496.06,2700.79 2468.5,2728.35 2468.5,2822.83 2547.24,2901.57 2547.24,3086.61 2500,3133.86 2429.13,3133.86 v1(2409.45,3153.54) 2440.94,3185.04 2830.71,3185.04 2850.39,3204.72 2921.26,3204.72 3000,3283.46 v1(3000,3377.95)
  MidLayer4 w5: v2(1456.69,3381.89) 1456.69,3500 1437.01,3519.68 1437.01,3535.43 1496.06,3594.49 1952.75,3594.49 2023.62,3523.63 v2(2023.62,3503.93) ; v1(2271.65,3500) 2271.65,3519.69 2401.57,3649.61 2937.39,3649.61 3000,3587 v1(3000,3377.95)
  Bottom Layer w5: v2(1456.69,3381.89) U7.23@1456.69,3452.76 ; v1(3000,3377.95) U11.1@3000,3452.76
BUS_A3: U3.C2 U4.M20 U6.24 U7.24 U10.2 U11.2 | length 5538.2
  Top Layer w5: U6.24@2055.12,3452.76 v2(2055.11,3527.55) ; U10.2@2303.15,3452.76 v1(2303.15,3523.62) ; U3.C2@2429.13,3134.84 2430.12,3134.85 v1(2448.82,3153.54)
  Top Layer w7.87: U4.M20@1779.53,1535.43 v1(1799.22,1555.12)
  MidLayer1 w5: v2(2055.11,3527.55) 2055.12,3507.87 2094.49,3468.5 2283.46,3468.5 2303.15,3488.19 v1(2303.15,3523.62)
  MidLayer2 w5: v1(1799.22,1555.12) 1858.27,1496.06 1913.39,1496.06 1940.95,1496.06 1956.7,1511.81 2078.74,1511.81 2090.55,1511.81 2125.98,1511.81 2401.57,1787.4 2401.57,2118.11 2519.68,2236.22 2519.68,2263.78 2527.56,2271.65 2527.56,2287.4 2480.31,2334.65 2480.31,2645.67 2507.87,2673.23 2507.87,2704.72 2480.31,2732.28 2480.31,2755.91 ; 2480.31,2744.09 2480.31,2818.9 2562.99,2901.57 2562.99,3090.55 2500,3153.54 v1(2448.82,3153.54) 2448.82,3169.29 2452.76,3173.23 2838.58,3173.23 2854.33,3188.98 2925.2,3188.98 3019.68,3283.46 3019.68,3385.83 3003.94,3401.57 v1(2968.5,3401.57)
  MidLayer4 w5: v2(1425.2,3405.51) 1425.2,3472.44 1405.51,3492.13 1405.51,3511.81 1417.32,3523.62 1417.32,3535.43 1488.19,3606.3 1976.37,3606.3 v2(2055.11,3527.55) ; v1(2303.15,3523.62) 2307.09,3523.62 2421.26,3637.8 2932.21,3637.79 2987,3583 2987,3420.07 v1(2968.5,3401.57)
  Bottom Layer w5: v2(1425.2,3405.51) U7.24@1425.2,3452.76 ; v1(2968.5,3401.57) U11.2@2968.5,3452.76
BUS_A4: U3.A2 U4.L25 U6.25 U7.25 U10.3 U11.3 | length 4788.4
  Top Layer w5: U4.L25@1976.38,1574.8 1996.07,1594.49 2078.74,1594.49 2090.55,1594.49 2185.04,1594.49 2322.83,1732.28 2322.83,2000 2519.68,2196.85 2519.68,2263.78 2527.56,2271.65 2527.56,2633.86 2547.24,2653.54 2547.24,2763.78 ; U6.25@2086.61,3452.76 v2(2086.61,3503.93) ; U10.3@2334.64,3452.76 v1(2334.64,3500) ; U3.A2@2507.87,3134.84 2550.19,3134.85 ; 2547.24,2748.03 2547.24,2807.09 2606.3,2866.14 2606.3,3078.74 2550.19,3134.85 ; v1(2550.19,3152.55) 2550.19,3134.85
  MidLayer1 w5: v1(2550.19,3152.55) 2731.29,3152.55 2937.01,3358.27 v1(2937.01,3370.08)
  MidLayer4 w5: v2(1393.7,3527.56) 1484.25,3618.11 1992.62,3618.11 2086.61,3524.12 v2(2086.61,3503.93) 2110.23,3480.32 2314.96,3480.32 v1(2334.64,3500) 2334.64,3535.43 2425.19,3625.98 2923.02,3625.98 2976,3573 2976,3441 2937.01,3402.01 v1(2937.01,3370.08)
  Bottom Layer w5: U7.25@1393.7,3452.76 v2(1393.7,3527.56) ; U11.3@2933.07,3452.76 U11.3@2933.07,3430.12 ; v1(2937.01,3370.08) 2937.01,3377.95 2937.01,3413.39 2933.07,3417.32 U11.3@2933.07,3430.12 ; U11.3@2937.01,3434.05 U11.3@2933.07,3430.12
BUS_A5: U3.B2 U4.K25 U6.26 U7.26 U10.4 U11.4 | length 4962.3
  Top Layer w5: U4.K25@1976.38,1614.17 1996.06,1633.86 2031.5,1633.86 2035.43,1629.92 2078.74,1629.92 2090.55,1629.92 2106.3,1629.92 2125.98,1610.24 2181.1,1610.24 2311.02,1740.16 2311.02,2003.94 2496.06,2188.98 2496.06,2263.78 2488.19,2271.65 2488.19,2610.24 2535.43,2657.48 2535.43,2767.72 ; U6.26@2118.11,3452.76 v2(2118.11,3527.55) ; U10.4@2366.14,3452.76 v1(2366.14,3523.62) ; U3.B2@2468.5,3134.84 2468.51,3133.86 v1(2488.19,3114.17) 2519.69,3114.17 2594.49,3039.37 2594.49,2870.08 2535.43,2811.02 2535.43,2755.91
  MidLayer1 w5: v2(2118.11,3527.55) 2165.34,3480.32 2279.53,3480.32 2291.34,3492.13 2291.34,3507.87 2281.65,3517.56 2281.65,3529.68 2299.21,3547.24 2342.52,3547.24 v1(2366.14,3523.62) ; v1(2488.19,3114.17) 2488.19,3133.86 2527.56,3173.23 2736.22,3173.23 2913.39,3350.39 v1(2913.39,3401.57)
  MidLayer4 w5: v2(1362.2,3405.51) 1362.2,3472.44 1342.52,3492.13 1342.52,3511.81 1460.63,3629.92 2015.74,3629.92 v2(2118.11,3527.55) ; v1(2366.14,3523.62) 2366.14,3535.43 2433.07,3602.36 2893.7,3602.36 2924.7,3571.36 2924.7,3524.11 2933.07,3515.75 2933.07,3421.26 v1(2913.39,3401.57)
  Bottom Layer w5: v2(1362.2,3405.51) U7.26@1362.2,3452.76 ; U11.4@2905.51,3448.82 U11.4@2901.57,3452.76 2901.57,3413.39 v1(2913.39,3401.57)
BUS_A6: U3.D3 U4.F21 U6.29 U7.29 U10.5 U11.5 | length 4761.4
  Top Layer w5: v2(2118.1,3850.39) U6.29@2118.11,3901.57 ; U10.5@2397.64,3452.76 v1(2397.64,3500)
  Top Layer w7.87: U4.F21@1818.9,1771.65 v1(1838.59,1791.34) ; U3.D3@2389.77,3095.48 v1(2409.45,3114.18)
  MidLayer1 w5: v1(2409.45,3114.18) 2425.2,3114.18 2429.13,3118.11 2429.13,3122.05 2440.94,3133.86 2472.44,3133.86 2523.62,3185.04 2732.28,3185.04 2881.89,3334.65 v1(2881.89,3366.14)
  MidLayer2 w5: v1(1838.59,1791.34) 1858.27,1811.03 1858.27,1866.14 1858.27,1968.51 1877.95,1988.19 1877.95,2031.5 1877.95,2039.37 1877.95,2055.12 2007.87,2185.04 2082.68,2185.04 2118.11,2220.47 2118.11,2263.78 2106.3,2275.59 2106.3,2291.34 2122.05,2307.09 2122.05,2645.67 2110.24,2657.48 2110.24,2673.23 2311.02,2874.02 2311.02,3082.68 2322.83,3094.49 2350.39,3094.49 2370.08,3114.18 v1(2409.45,3114.18)
  MidLayer3 w5: v2(2118.1,3850.39) 2118.11,3822.84 2397.64,3543.31 v1(2397.64,3500)
  MidLayer4 w5: v2(1362.2,3948.82) 1362.2,3885.83 1342.52,3866.14 1342.52,3842.52 1460.63,3724.41 2011.81,3724.41 2118.1,3830.7 v2(2118.1,3850.39) ; v1(2397.64,3500) 2397.64,3535.93 2440.45,3578.74 2854.33,3578.74 2866.14,3566.93 2866.14,3555.86 2889.76,3532.24 2889.76,3515.75 2881.89,3507.87 v1(2881.89,3366.14)
  Bottom Layer w5: U7.29@1362.2,3901.59 v2(1362.2,3948.82) ; U11.5@2870.08,3452.76 2870.08,3433.07 2881.89,3421.26 v1(2881.89,3366.14)
BUS_A7: U3.C3 U4.L20 U6.30 U7.30 U10.18 U11.18 | length 4996.7
  Top Layer w5: v2(2086.61,3826.77) U6.30@2086.61,3901.57 ; U10.18@2807.09,3452.76 2807.09,3496.06 2826.77,3515.75 2826.77,3535.43 v1(2846.46,3555.12)
  Top Layer w7.87: U4.L20@1779.53,1574.8 v1(1799.22,1594.49) ; U3.C3@2429.14,3095.48 v1(2448.82,3114.17)
  MidLayer2 w5: v1(1799.22,1594.49) 1818.9,1574.8 2005.91,1574.8 2061.03,1629.92 2078.74,1629.92 2090.55,1629.92 2106.3,1629.92 2377.95,1901.57 2377.95,2133.86 2456.69,2212.6 2456.69,2263.78 2468.5,2275.59 2468.5,2295.28 2456.69,2307.09 2456.69,2826.77 2507.87,2877.95 2507.87,3082.68 2496.06,3094.49 2468.5,3094.49 v1(2448.82,3114.17) ; v1(2688.98,3295.28) 2795.28,3401.57 2795.28,3484.25 2826.77,3515.75 2826.77,3535.43 v1(2846.46,3555.12)
  MidLayer3 w5: v2(2086.61,3826.77) 2086.61,3858.26 2098.43,3870.08 2125.98,3870.08 2137.8,3858.27 2137.8,3826.77 2409.45,3555.12 2409.45,3515.75 2460.63,3464.57 v2(2460.63,3401.57)
  MidLayer4 w5: v2(1393.7,3826.77) 1484.25,3736.22 1996.06,3736.22 v2(2086.61,3826.77) ; v2(2460.63,3401.57) 2519.68,3460.63 2771.65,3460.63 2826.77,3515.75 2826.77,3535.43 v1(2846.46,3555.12)
  Bottom Layer w5: v2(1393.7,3826.77) U7.30@1393.7,3901.57 ; v1(2448.82,3114.17) 2559.06,3224.41 2606.3,3224.41 2610.24,3228.35 2629.92,3248.03 2629.92,3263.78 2641.73,3275.59 2657.48,3275.59 2669.29,3287.4 2669.29,3291.34 2673.23,3295.28 v1(2688.98,3295.28) ; v2(2460.63,3401.57) U11.18@2460.63,3452.76 U11.18@2460.63,3472.44
BUS_A8: U3.A3 U4.J26 U6.31 U7.31 U10.19 U11.19 | length 4743.7
  Top Layer w5: U4.J26@2015.75,1653.54 2031.5,1653.54 2039.37,1645.67 2078.74,1645.67 2090.06,1645.67 2114.17,1645.67 2118.11,1649.61 2192.91,1649.61 2299.21,1755.91 2299.21,2007.87 2456.69,2165.35 2456.69,2263.78 2464.57,2271.65 2464.57,2602.36 2523.62,2661.42 2523.62,2814.96 2582.68,2874.02 2582.68,3019.68 v1(2527.56,3074.8) ; v2(2055.11,3850.39) U6.31@2055.12,3901.57 ; U10.19@2838.58,3452.76 2838.58,3472.44 2858.27,3492.13 2858.27,3511.81 v1(2870.08,3523.62)
  Top Layer w7.87: U3.A3@2507.88,3095.48 v1(2527.56,3074.8)
  MidLayer2 w5: v1(2688.98,3240.16) 2708.66,3240.16 2826.77,3358.27 2826.77,3366.14 2826.77,3437.01 2870.08,3480.31 v1(2870.08,3523.62)
  MidLayer3 w5: v2(2055.11,3850.39) 2055.11,3818.9 2080.55,3793.46 2123.86,3793.46 2370.08,3547.24 2385.83,3531.5 2385.83,3515.28 2385.36,3515.28 2377.95,3507.87 2377.95,3480.32 2429.13,3429.13 v1(2429.13,3377.95)
  MidLayer4 w5: v2(1425.2,3948.82) 1425.2,3885.83 1421.26,3881.89 1405.51,3866.14 1405.51,3842.52 1417.32,3830.71 1417.32,3822.83 1492.13,3748.03 1976.38,3748.03 2055.11,3826.77 v2(2055.11,3850.39) ; v1(2429.13,3377.95) 2448.82,3358.27 2511.81,3358.27 2594.49,3440.94 2811.02,3440.94 2858.27,3488.19 2858.27,3511.81 v1(2870.08,3523.62)
  Bottom Layer w5: U7.31@1425.2,3901.57 v2(1425.2,3948.82) ; v1(2429.13,3377.95) U11.19@2429.13,3452.76 ; v1(2527.56,3074.8) 2527.56,3094.49 2673.23,3240.16 v1(2688.98,3240.16)
BUS_A9: U3.B6 U4.M24 U6.32 U7.32 U10.20 U11.20 | length 5180.4
  Top Layer w5: v2(2023.62,3826.77) U6.32@2023.62,3901.57 ; U10.20@2870.08,3452.76 2870.08,3496.06 2901.57,3527.56 v1(2901.57,3562.99)
  Top Layer w7.87: U4.M24@1937.01,1535.43 v1(1956.7,1555.12) ; U3.B6@2468.5,2977.36 v1@2488.19,2957.68
  MidLayer1 w5: v1(1956.7,1555.12) 1996.07,1555.12 2039.37,1598.43 2078.74,1598.43 2090.55,1598.43 2169.29,1598.43 2200.79,1629.92 2200.79,1649.61 2299.21,1748.03 2299.21,2098.43 2457.07,2256.28 2457.07,2263.4 2456.69,2263.78 2468.5,2275.59 2468.5,2322.83 2519.68,2374.02 2519.68,2732.28 ; v1@2488.19,2957.68 2488.68,2957.19 2507.87,2938 2507.87,2937.01 2507.88,2889.75 2519.66,2877.98 2519.69,2708.66
  MidLayer3 w5: v2(2023.62,3826.77) 2066.93,3783.46 2102.36,3783.46 2122.05,3763.78 2346.46,3539.37 2346.46,3515.75 2366.14,3496.06 2366.14,3433.07 v2(2397.64,3401.57) ; v1(2850.39,3224.41) 2850.39,3362.2 2881.89,3393.7 2881.89,3507.87 2901.57,3527.56 ; 2901.57,3527.56 v1(2901.57,3562.99)
  MidLayer4 w5: v2(1456.69,3948.82) 1456.69,3854.33 1437.01,3834.65 1437.01,3818.9 1496.06,3759.84 1956.69,3759.84 v2(2023.62,3826.77) ; v2(2397.64,3401.57) 2397.64,3358.27 2429.13,3326.77 2877.95,3326.77 2905.51,3354.33 2905.51,3377.95 2893.7,3389.76 2893.7,3464.57 2921.26,3492.13 2921.26,3507.87 2913.39,3515.75 2913.39,3551.18 v1(2901.57,3562.99)
  Bottom Layer w5: U7.32@1456.69,3901.57 v2(1456.69,3948.82) ; v2(2397.64,3401.57) U11.20@2397.64,3452.76 ; v1(2488.19,2956.69) 2507.87,2976.38 2555.12,2976.38 2570.87,2992.13 2570.87,3055.12 2740.16,3224.41 v1(2850.39,3224.41)
BUS_A10: U3.A6 U4.H25 U6.33 U7.33 U10.21 U11.21 | length 4762.6
  Top Layer w5: U4.H25@1976.38,1692.91 1996.06,1712.6 2027.56,1712.6 2047.24,1692.91 2078.74,1692.91 2090.55,1692.91 2177.17,1692.91 2263.78,1779.53 2263.78,2019.69 2370.08,2125.98 2370.08,2263.78 2362.2,2271.65 2362.2,2291.34 2429.13,2358.27 2429.13,2614.17 2456.69,2641.73 2456.69,2752.14 ; v2(1992.12,3850.39) U6.33@1992.13,3901.57 ; 2456.69,2740.16 2456.69,2795.27 2547.24,2885.83 2547.24,2937.01 v1(2527.56,2956.69) v1@2527.56,2957.68 ; U10.21@2901.57,3452.76 v1(2901.57,3500)
  Top Layer w7.87: U3.A6@2507.87,2977.36 v1@2527.56,2957.68
  MidLayer2 w5: v1(2870.08,3263.78) 2870.08,3318.9 2901.57,3350.39 2901.57,3381.89 2893.7,3389.76 2893.7,3468.5 2901.57,3476.38 v1(2901.57,3500)
  MidLayer3 w5: v2(1992.12,3850.39) 1992.12,3811.03 2031.5,3771.65 2098.43,3771.65 2322.83,3547.24 2322.83,3515.75 2314.96,3507.87 2314.96,3448.82 2366.14,3397.64 v1(2366.14,3377.95)
  MidLayer4 w5: v2(1488.19,3850.39) 1488.19,3814.96 1531.5,3771.65 1937.01,3771.65 1992.12,3826.77 v2(1992.12,3850.39) ; v1(2366.14,3377.95) 2366.14,3496.06 2385.36,3515.28 2385.83,3515.28 2385.83,3540.11 2436.27,3590.55 2862.2,3590.55 2877.95,3574.8 2877.95,3559.06 2901.57,3535.43 v1(2901.57,3500)
  Bottom Layer w5: v2(1488.19,3850.39) U7.33@1488.19,3901.57 ; v1(2366.14,3377.95) U11.21@2366.14,3452.76 ; v1(2527.56,2956.69) 2562.99,2956.69 2598.43,2992.13 2598.43,3066.93 2736.22,3204.72 2858.27,3204.72 2870.08,3216.54 v1(2870.08,3263.78)
BUS_A11: U3.C6 U4.L23 U6.34 U7.34 U10.22 U11.22 | length 5084.9
  Top Layer w5: v2(1960.62,3826.77) U6.34@1960.63,3901.57 ; U10.22@2933.07,3452.76 2933.07,3519.68 v1(2944.88,3531.5)
  Top Layer w7.87: U4.L23@1897.64,1574.8 v1(1917.33,1594.49) ; U3.C6@2429.13,2977.36 v1@2448.82,2957.68
  MidLayer1 w5: v1(1917.33,1594.49) 1937.01,1614.17 1980.32,1614.17 2019.69,1653.54 2078.74,1653.54 2090.55,1653.54 2188.98,1653.54 2287.4,1751.97 2287.4,2102.36 2433.07,2248.03 2433.07,2263.78 2421.26,2275.59 2421.26,2299.21 2507.87,2385.83 2507.87,2870.08 2468.51,2909.44 2468.51,2937.99 2449.31,2957.19 v1@2448.82,2957.68
  MidLayer2 w5: v1(2937.01,3259.84) 2937.01,3338.58 2952.76,3354.33 2956.69,3358.27 2956.69,3381.89 2944.88,3393.7 v1(2944.88,3531.5)
  MidLayer3 w5: v2(1960.62,3826.77) 2027.56,3759.84 2094.49,3759.84 2279.53,3574.8 2279.53,3519.68 2291.34,3507.87 2291.34,3444.88 v2(2334.65,3401.57)
  MidLayer4 w5: v2(1519.68,3948.82) 1519.68,3854.33 1500,3834.65 1500,3818.9 1535.43,3783.46 1917.32,3783.46 v2(1960.62,3826.77) ; v2(2334.65,3401.57) 2334.65,3472.44 2354.33,3492.13 2354.33,3507.87 2346.46,3515.75 2346.46,3531.5 2429.13,3614.17 2897.64,3614.17 2944.88,3566.93 v1(2944.88,3531.5) ; v1(2448.82,2956.69) 2468.5,2976.38 2649.61,2976.38 2858.27,3185.04 2909.45,3185.04 2937.01,3212.6 v1(2937.01,3259.84)
  Bottom Layer w5: U7.34@1519.68,3901.57 v2(1519.68,3948.82) ; v2(2334.65,3401.57) U11.22@2334.65,3452.76
BUS_A12: U3.D6 U4.K24 U6.22 U7.22 U10.23 U11.23 | length 5508.6
  Top Layer w5: U6.22@1992.13,3452.76 v2(1992.12,3527.55) ; v2(2933.07,3850.39) U10.23@2933.07,3901.57
  Top Layer w7.87: U4.K24@1937.01,1614.17 v1(1956.7,1633.86) ; U3.D6@2389.76,2977.36 v1@2409.45,2957.68
  MidLayer1 w5: v1(1956.7,1633.86) 1984.25,1633.86 2019.69,1669.29 2078.74,1669.29 2090.55,1669.29 2188.98,1669.29 2259.84,1740.16 ; 2204.72,1685.04 2275.59,1755.91 2275.59,2106.3 2393.7,2224.41 2393.7,2263.78 2405.51,2275.59 2405.51,2303.15 2417.32,2314.96 2417.32,2665.35 2433.07,2681.1 2433.07,2696.85 2393.7,2736.22 2393.7,2874.02 2429.14,2909.46 2429.14,2937 v1(2409.45,2956.69) 2409.45,2957.68 v1@2409.94,2957.19
  MidLayer2 w5: v2(1992.12,3527.55) 2023.62,3559.06 2141.73,3559.06 2314.96,3732.28 2314.96,3834.64 2326.77,3846.46 v2(2326.77,3952.76) ; v2(2933.07,3850.39) 2933.07,3610.24 3043.31,3500 3043.31,3240.16 v1(2988.19,3185.04)
  MidLayer4 w5: v2(1488.19,3503.94) 1488.19,3539.37 1531.5,3582.68 1937,3582.68 v2(1992.12,3527.55) ; v2(2326.77,3952.76) 2326.77,3933.07 2334.65,3925.2 2334.65,3854.33 2354.33,3834.65 2354.33,3811.02 2370.08,3795.28 2913.39,3795.28 2933.07,3814.96 v2(2933.07,3850.39) ; v1(2409.45,2956.69) 2429.13,2937.01 2653.54,2937.01 2795.28,3078.74 2964.57,3078.74 2988.19,3102.36 v1(2988.19,3185.04)
  Bottom Layer w5: U7.22@1488.19,3452.76 v2(1488.19,3503.94) ; v2(2326.77,3952.76) 2326.77,3929.13 2334.65,3921.26 U11.23@2334.65,3901.57
BUS_A13: U3.B7 U4.G25 U6.35 U7.35 U10.24 U11.24 | length 4999
  Top Layer w5: v2(1929.13,3850.39) U6.35@1929.13,3901.57 ; U4.G25@1976.38,1732.28 1996.06,1751.97 2031.5,1751.97 2035.43,1748.03 2078.74,1748.03 2090.55,1748.03 2110.24,1748.03 2114.17,1744.09 2185.04,1744.09 2240.16,1799.21 2240.16,2027.56 2307.09,2094.49 2307.09,2263.78 2299.21,2271.65 2299.21,2290.85 2405.51,2397.14 2405.51,2622.05 2433.07,2649.61 2433.07,2756.79 ; 2433.07,2740.16 2433.07,2807.09 2488.19,2862.21 2488.19,2918.31 U3.B7@2468.5,2937.99 ; v2(2901.57,3826.77) U10.24@2901.57,3901.57
  MidLayer1 w5: v2(1929.13,3850.39) 1929.13,3913.39 2011.81,3996.06 2322.83,3996.06 v2(2366.14,3952.76)
  MidLayer2 w5: v2(2901.57,3826.77) 2913.39,3814.96 2913.39,3606.3 3031.5,3488.19 3031.5,3259.84 v1(2956.69,3185.04)
  MidLayer4 w5: v2(1551.18,3948.82) 1551.18,3881.89 1531.5,3862.2 1531.5,3842.52 1578.74,3795.28 1897.64,3795.28 1929.13,3826.77 v2(1929.13,3850.39) ; v2(2366.14,3952.76) 2421.26,4007.87 2834.65,4007.87 2858.27,3984.25 2858.27,3968.5 2850.39,3960.63 2850.39,3905.51 2889.76,3866.14 2889.76,3838.58 v2(2901.57,3826.77)
  Bottom Layer w5: U7.35@1551.18,3881.89 U7.35@1551.18,3901.57 v2(1551.18,3948.82) ; U11.24@2366.14,3901.57 v2(2366.14,3952.76) ; v1(2488.19,2917.32) 2507.87,2897.64 2559.06,2897.64 2704.72,3043.31 2818.9,3043.31 2866.14,3090.55 2921.26,3090.55 2956.69,3125.98 v1(2956.69,3185.04)
BUS_A14: U3.A7 U4.G26 U6.36 U7.36 U10.25 U11.25 | length 4618.6
  Top Layer w5: v2(1897.63,3826.77) U6.36@1897.64,3901.57 ; U4.G26@2015.75,1732.28 2078.74,1732.28 2090.55,1732.28 2188.98,1732.28 2251.97,1795.28 2251.97,2023.62 2330.71,2102.36 2330.71,2263.78 2338.58,2271.65 2338.58,2299.21 2417.32,2377.95 2417.32,2618.11 2444.88,2645.67 2444.88,2754.47 ; 2444.88,2744.09 2444.88,2799.21 2527.56,2881.89 v1(2527.56,2917.32) v1@2527.56,2918.31 ; v2(2870.08,3850.39) U10.25@2870.08,3901.57
  Top Layer w7.87: U3.A7@2507.87,2937.99 v1@2527.56,2918.31
  MidLayer1 w5: v2(1897.63,3826.77) 1897.64,3921.26 1917.32,3940.94 1917.32,3956.69 1909.45,3964.57 1909.45,3980.32 1921.26,3992.13 1988.19,3992.13 2003.94,4007.87 2342.52,4007.87 v2(2397.64,3952.76)
  MidLayer3 w5: v2(2870.08,3850.39) 2881.89,3838.58 2881.89,3814.96 2921.26,3775.59 2921.26,3555.12 2913.39,3547.24 2913.39,3515.75 2921.26,3507.87 2921.26,3444.88 2893.7,3417.32 2893.7,3389.76 2901.57,3381.89 2901.57,3354.33 2889.76,3342.52 v1(2889.76,3224.41)
  MidLayer4 w5: v2(1582.68,3830.71) 1606.3,3807.09 1877.95,3807.09 v2(1897.63,3826.77) ; v2(2397.64,3952.76) 2440.94,3996.06 2791.34,3996.06 2838.58,3948.82 2838.58,3881.89 v2(2870.08,3850.39)
  Bottom Layer w5: v2(1582.68,3830.71) U7.36@1582.68,3901.57 ; U11.25@2397.64,3901.57 v2(2397.64,3952.76) ; v1(2527.56,2917.32) 2551.18,2917.32 2616.5,2982.65 2616.5,3069.26 2736.22,3188.98 2870.08,3188.98 2889.76,3208.66 v1(2889.76,3224.41)
BUS_A15: U3.C7 U4.F25 U6.20 U7.20 U10.26 U11.26 | length 4766.8
  Top Layer w5: U6.20@1929.13,3452.76 v2(1929.13,3527.55) ; U4.F25@1976.38,1771.65 1996.06,1791.34 2031.5,1791.34 2043.31,1779.53 2078.74,1779.53 2090.55,1779.53 2114.17,1779.53 2125.98,1767.72 2177.17,1767.72 2216.54,1807.09 2216.54,2208.66 2244.09,2236.22 2244.09,2263.78 2236.22,2271.65 2236.22,2291.34 2358.27,2413.39 2358.27,2669.29 2370.08,2681.1 2370.08,2795.28 2448.82,2874.02 v1(2448.82,2917.32) 2448.82,2918.31 U3.C7@2429.13,2937.99 ; v2(2838.58,3826.77) U10.26@2838.58,3901.57
  MidLayer2 w5: v2(1929.13,3527.55) 1972.44,3570.87 2129.92,3570.87 2291.34,3732.28 2291.34,3834.65 2283.46,3842.52 2283.46,3881.89 2293.31,3891.73 2307.09,3905.51 2307.09,3960.63 2318.9,3972.44 2409.45,3972.44 v2(2429.13,3952.76) ; v1(2681.1,3267.72) 2696.85,3267.72 2811.02,3381.89 2811.02,3440.94 2858.27,3488.19 2858.27,3507.87 2850.39,3515.75 2850.39,3531.5 2866.14,3547.25 2866.14,3574.8 2846.46,3594.49 2846.46,3673.23 2834.64,3685.04 2834.64,3704.72 2838.58,3708.66 v2(2838.58,3826.77)
  MidLayer3 w5: v1(2448.82,2917.32) 2468.5,2937.01 2535.43,2937.01 2665.35,3066.93 2665.35,3244.09 2669.29,3248.03 2669.29,3255.91 v1(2681.1,3267.72)
  MidLayer4 w5: v2(1551.18,3405.51) 1551.18,3476.38 1531.5,3496.06 1531.5,3511.81 1543.31,3523.62 1543.31,3535.43 1566.93,3559.06 1897.63,3559.06 v2(1929.13,3527.55) ; v2(2429.13,3952.76) 2429.13,3929.13 2472.44,3885.83 2744.09,3885.83 2803.15,3826.77 v2(2838.58,3826.77)
  Bottom Layer w5: v2(1551.18,3405.51) U7.20@1551.18,3452.76 ; U11.26@2429.13,3901.57 v2(2429.13,3952.76)
BUS_A16: U3.D7 U4.D26 U6.21 U7.21 U10.27 U11.27 | length 4815.6
  Top Layer w5: U6.21@1960.63,3452.76 v2(1960.63,3503.93) ; U4.D26@2015.75,1850.39 2031.49,1850.39 2055.12,1826.77 2078.74,1826.77 2090.55,1826.77 2106.3,1826.77 2165.35,1885.83 2165.35,2220.47 2141.73,2244.09 2141.73,2263.78 2153.54,2275.59 2153.54,2303.15 2307.09,2456.69 2307.09,2858.27 2330.71,2881.89 2330.71,2944.88 2343.51,2957.68 v1@2370.08,2957.68 ; v2(2807.09,3850.39) U10.27@2807.09,3901.57
  Top Layer w7.87: v1@2370.08,2957.68 2370.57,2957.19 U3.D7@2389.76,2937.99
  MidLayer2 w5: v2(1960.63,3503.93) 1925.2,3503.93 1909.45,3519.68 1909.45,3535.43 1925.2,3551.18 1956.69,3582.68 2118.11,3582.68 2251.97,3716.54 2251.97,3877.95 2291.34,3917.32 2291.34,3960.63 2314.96,3984.25 2433.07,3984.25 2460.63,3956.69 v2(2460.63,3952.76) ; v1(2649.61,3295.28) 2755.91,3401.57 2755.91,3507.87 2763.78,3515.75 2763.78,3531.5 2751.97,3543.31 2751.97,3562.99 2803.15,3614.17 2803.15,3677.17 2811.02,3685.04 2811.02,3704.72 2807.09,3708.66 v2(2807.09,3850.39)
  MidLayer4 w5: v2(1519.68,3405.51) 1519.68,3500 1500,3519.68 1500,3535.43 1535.43,3570.87 1913.38,3570.87 1960.63,3523.63 v2(1960.63,3503.93) ; v1(2370.08,2956.69) 2370.08,2996.06 2350.39,3015.75 2350.39,3043.31 2362.2,3055.12 2377.95,3055.12 2389.76,3066.93 2389.76,3082.68 2401.57,3094.49 2523.62,3094.49 2629.92,3200.79 2629.92,3275.59 v1(2649.61,3295.28) ; v2(2460.63,3952.76) 2460.63,3929.13 2472.44,3917.32 2783.46,3917.32 2807.09,3893.7 v2(2807.09,3850.39)
  Bottom Layer w5: v2(1519.68,3405.51) U7.21@1519.68,3452.76 ; U11.27@2460.63,3901.57 v2(2460.63,3952.76)
BUS_A17: U3.E7 U4.E25 U10.42 U11.42 | length 3994
  Top Layer w5: U4.E25@1976.38,1811.02 1996.06,1830.71 2031.5,1830.71 2051.18,1811.02 2078.74,1811.02 2090.55,1811.02 2110.24,1811.02 2192.91,1893.7 2192.91,2251.97 2173.23,2271.65 2173.23,2287.4 2318.9,2433.07 2318.9,2807.09 2370.08,2858.27 v1(2370.08,2917.32) ; v2(2334.64,3826.77) U10.42@2334.64,3901.57
  Top Layer w7.87: U3.E7@2350.39,2937.99 v1(2370.08,2917.32)
  MidLayer3 w5: v2(2933.07,3952.76) 2933.07,3877.95 2972.44,3838.58 2972.44,3437.01 2948.82,3413.39 2948.82,3389.76 2956.69,3381.89 v1(2956.69,3311.02)
  MidLayer4 w5: v2(2334.64,3826.77) 2334.64,3807.09 2358.27,3783.46 2917.32,3783.46 2952.76,3818.9 2952.76,3885.83 2933.07,3905.51 v2(2933.07,3952.76) ; v1(2370.08,2917.32) 2389.76,2897.64 2649.61,2897.64 2740.16,2988.19 2933.07,2988.19 3007.87,3062.99 3007.87,3259.84 v1(2956.69,3311.02)
  Bottom Layer w5: U11.42@2933.07,3901.57 v2(2933.07,3952.76)
BUS_A18: U3.B3 U4.K22 U10.43 U11.43 | length 4110
  Top Layer w5: v2(2303.15,3850.39) U10.43@2303.15,3901.57 ; v1(2488.19,3074.8) v1@2488.19,3075.8
  Top Layer w7.87: U4.K22@1858.27,1614.17 v1(1877.96,1633.86) ; U3.B3@2468.5,3095.47 v1@2488.19,3075.79
  MidLayer2 w5: v1(1877.96,1633.86) 1897.64,1653.54 2078.74,1653.54 2090.55,1653.54 2114.17,1653.54 2366.14,1905.51 2366.14,2141.73 2437.01,2212.6 2437.01,2259.84 2421.26,2275.59 2421.26,2295.28 2444.88,2318.9 2444.88,2673.23 2444.88,2842.52 2448.82,2846.46 2448.82,2885.83 2468.5,2905.51 2468.5,2976.38 2468.5,3055.12 v1(2488.19,3074.8)
  MidLayer3 w5: v2(2964.57,3952.76) 2964.57,3866.14 2984.25,3846.46 2984.25,3417.32 2988.19,3413.39 2988.19,3393.7 2976.38,3381.89 v1(2976.38,3334.65)
  MidLayer4 w5: v2(2303.15,3850.39) 2303.15,3822.83 2354.33,3771.65 2921.26,3771.65 2964.57,3814.96 v2(2964.57,3952.76)
  Bottom Layer w5: v1(2488.19,3074.8) 2507.87,3055.12 2555.12,3055.12 2816.68,3316.68 2852.11,3316.68 2877.95,3342.52 2933.07,3342.52 2940.94,3334.65 v1(2976.38,3334.65) ; U11.43@2964.57,3901.57 v2(2964.57,3952.76)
